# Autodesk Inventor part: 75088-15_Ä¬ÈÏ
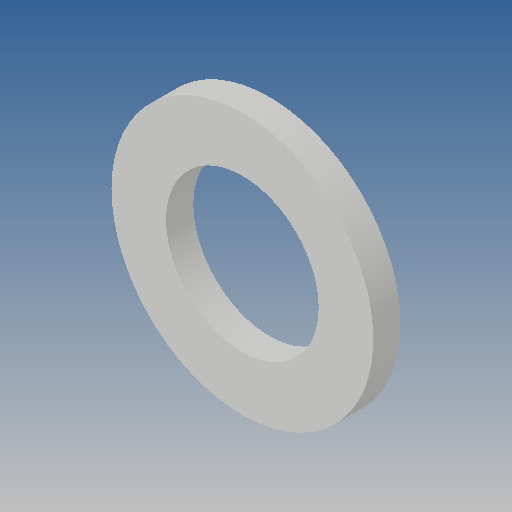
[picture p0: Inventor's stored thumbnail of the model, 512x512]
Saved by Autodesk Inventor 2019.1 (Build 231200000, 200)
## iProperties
Created: 2010-06
Part Number: 75088-15_Ä¬ÈÏ
Material: Ogólny
Document SubType Name: Modeling
Designer: CADENGINEERING4
Density: 1 g/cm^3
Appearance: Domyślna
Author: CADENGINEERING4
Revision Number: ÈÎºÎ
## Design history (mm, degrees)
feature "NONE"
node "Bryła1"
